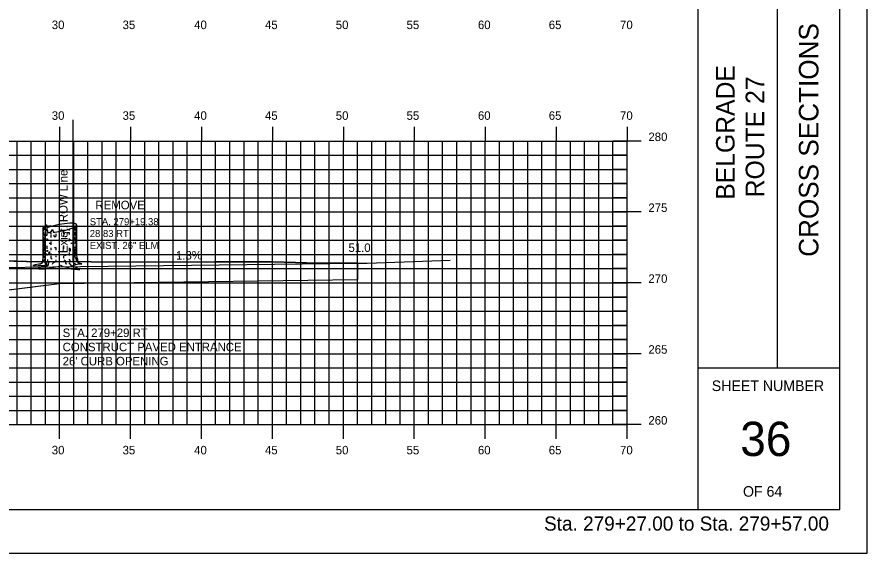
# Model space of a CAD drawing. Extents: x 854899 to 855069, y 366268 to 366378.
# Drawn here: x 855008.8 to 855068.7, y 366268.2 to 366306 of the extents above; entities that cross this region are included whole.
import ezdxf

# ---------------------------------------------------------------- set-up
doc = ezdxf.new("R2010")
doc.units = 0
for name, color, linetype in [('ANNOTATION', 7, 'Continuous'), ('BORDER', 7, 'Continuous'), ('D_Roadway_Drive_Gravel_RT', 7, 'Continuous'), ('D_Roadway_Drive_SubGrade', 7, 'Continuous'), ('D_Text_Monospaced', 7, 'Continuous'), ('D_Text_Standard', 7, 'Continuous'), ('E_ROW_Line', 7, 'Continuous'), ('H_V ANNOTATION', 7, 'Continuous'), ('HIGHWAY_TITLE', 7, 'Continuous'), ('JUNK COM EXC', 7, 'Continuous'), ('MAJOR', 7, 'Continuous'), ('MINOR', 7, 'Continuous'), ('PLOT BOUNDARY', 7, 'Continuous'), ('S_Roadway_Centerline', 7, 'Continuous'), ('S_Trees_Decid_Pay', 7, 'Continuous')]:
    doc.layers.add(name, color=color, linetype=linetype)

msp = doc.modelspace()

# ---------------------------------------------------------------- linework, layer by layer
at = {"layer": 'BORDER'}
for p, q in [((855056.774, 366271.236), (855056.774, 366376.239)), ((855066.774, 366271.236), (855066.774, 366376.236)), ((855062.365, 366281.239), (855062.365, 366316.239)), ((855056.774, 366281.239), (855066.774, 366281.239)), ((854906.774, 366271.236), (855066.774, 366271.236))]:
    msp.add_line(p, q, dxfattribs=at)
at = {"layer": 'D_Roadway_Drive_Gravel_RT'}
for p, q in [((855005.774, 366288.293), (855032.774, 366288.63)), ((855011.774, 366287.201), (855032.774, 366287.463))]:
    msp.add_line(p, q, dxfattribs=at)
at = {"layer": 'D_Roadway_Drive_SubGrade'}
for p, q in [((855032.774, 366288.63), (855032.774, 366287.463)), ((855001.774, 366285.94), (855011.774, 366287.201))]:
    msp.add_line(p, q, dxfattribs=at)
at = {"layer": 'E_ROW_Line'}
msp.add_line((855012.733, 366288.733), (855012.733, 366298.733), dxfattribs=at)
at = {"layer": 'JUNK COM EXC'}
msp.add_lwpolyline([(855001.774, 366285.94), (855011.774, 366287.201), (855032.774, 366287.463), (855032.774, 366288.63), (855029.947, 366288.626), (855028.392, 366288.676), (855026.837, 366288.727), (855022.702, 366288.715), (855018.567, 366288.702), (855014.002, 366288.726), (855009.438, 366288.75), (855008.079, 366288.784), (855006.72, 366288.819), (855003.306, 366288.619), (855001.774, 366288.529)], close=True, dxfattribs=at)
at = {"layer": 'MAJOR'}
for p, q in [((855011.774, 366298.238), (855011.774, 366297.236)), ((855016.774, 366298.238), (855016.774, 366297.236)), ((855021.774, 366298.238), (855021.774, 366297.236)), ((855026.774, 366298.238), (855026.774, 366297.236)), ((855031.774, 366298.238), (855031.774, 366297.236)), ((855036.774, 366298.238), (855036.774, 366297.236)), ((855041.774, 366298.238), (855041.774, 366297.236)), ((855046.774, 366298.238), (855046.774, 366297.236)), ((855051.774, 366298.238), (855051.774, 366297.236)), ((854911.774, 366297.236), (855051.774, 366297.236)), ((854911.774, 366297.236), (855051.774, 366297.236)), ((855011.774, 366277.236), (855011.774, 366297.236)), ((855016.774, 366277.236), (855016.774, 366297.236)), ((855021.774, 366277.236), (855021.774, 366297.236)), ((855026.774, 366277.236), (855026.774, 366297.236)), ((855031.774, 366277.236), (855031.774, 366297.236)), ((855036.774, 366277.236), (855036.774, 366297.236)), ((855041.774, 366277.236), (855041.774, 366297.236)), ((855046.774, 366277.236), (855046.774, 366297.236)), ((855052.776, 366297.236), (855050.772, 366297.236)), ((855051.774, 366277.236), (855051.774, 366297.236)), ((855051.774, 366277.236), (855051.774, 366297.236)), ((854911.774, 366292.236), (855051.774, 366292.236)), ((855052.776, 366292.236), (855050.772, 366292.236)), ((854911.774, 366287.236), (855051.774, 366287.236)), ((855052.776, 366287.236), (855050.772, 366287.236)), ((854911.774, 366282.236), (855051.774, 366282.236)), ((855052.776, 366282.236), (855050.772, 366282.236)), ((854911.774, 366277.236), (855051.774, 366277.236)), ((854911.774, 366277.236), (855051.774, 366277.236)), ((855011.774, 366276.234), (855011.774, 366277.236)), ((855016.774, 366276.234), (855016.774, 366277.236)), ((855021.774, 366276.234), (855021.774, 366277.236)), ((855026.774, 366276.234), (855026.774, 366277.236)), ((855031.774, 366276.234), (855031.774, 366277.236)), ((855036.774, 366276.234), (855036.774, 366277.236)), ((855041.774, 366276.234), (855041.774, 366277.236)), ((855046.774, 366276.234), (855046.774, 366277.236)), ((855052.776, 366277.236), (855050.772, 366277.236)), ((855051.774, 366276.234), (855051.774, 366277.236))]:
    msp.add_line(p, q, dxfattribs=at)
at = {"layer": 'MINOR'}
for p, q in [((855008.774, 366277.236), (855008.774, 366297.236)), ((855009.774, 366277.236), (855009.774, 366297.236)), ((855010.774, 366277.236), (855010.774, 366297.236)), ((855012.774, 366277.236), (855012.774, 366297.236)), ((855013.774, 366277.236), (855013.774, 366297.236)), ((855014.774, 366277.236), (855014.774, 366297.236)), ((855015.774, 366277.236), (855015.774, 366297.236)), ((855017.774, 366277.236), (855017.774, 366297.236)), ((855018.774, 366277.236), (855018.774, 366297.236)), ((855019.774, 366277.236), (855019.774, 366297.236)), ((855020.774, 366277.236), (855020.774, 366297.236)), ((855022.774, 366277.236), (855022.774, 366297.236)), ((855023.774, 366277.236), (855023.774, 366297.236)), ((855024.774, 366277.236), (855024.774, 366297.236)), ((855025.774, 366277.236), (855025.774, 366297.236)), ((855027.774, 366277.236), (855027.774, 366297.236)), ((855028.774, 366277.236), (855028.774, 366297.236)), ((855029.774, 366277.236), (855029.774, 366297.236)), ((855030.774, 366277.236), (855030.774, 366297.236)), ((855032.774, 366277.236), (855032.774, 366297.236)), ((855033.774, 366277.236), (855033.774, 366297.236)), ((855034.774, 366277.236), (855034.774, 366297.236)), ((855035.774, 366277.236), (855035.774, 366297.236)), ((855037.774, 366277.236), (855037.774, 366297.236)), ((855038.774, 366277.236), (855038.774, 366297.236)), ((855039.774, 366277.236), (855039.774, 366297.236)), ((855040.774, 366277.236), (855040.774, 366297.236)), ((855042.774, 366277.236), (855042.774, 366297.236)), ((855043.774, 366277.236), (855043.774, 366297.236)), ((855044.774, 366277.236), (855044.774, 366297.236)), ((855045.774, 366277.236), (855045.774, 366297.236)), ((855047.774, 366277.236), (855047.774, 366297.236)), ((855048.774, 366277.236), (855048.774, 366297.236)), ((855049.774, 366277.236), (855049.774, 366297.236)), ((855050.774, 366277.236), (855050.774, 366297.236)), ((854911.774, 366296.236), (855051.774, 366296.236)), ((855051.774, 366296.236), (855050.772, 366296.236)), ((854911.774, 366295.236), (855051.774, 366295.236)), ((855051.774, 366295.236), (855050.772, 366295.236)), ((854911.774, 366294.236), (855051.774, 366294.236)), ((855051.774, 366294.236), (855050.772, 366294.236)), ((854911.774, 366293.236), (855051.774, 366293.236)), ((855051.774, 366293.236), (855050.772, 366293.236)), ((854911.774, 366291.236), (855051.774, 366291.236)), ((855051.774, 366291.236), (855050.772, 366291.236)), ((854911.774, 366290.236), (855051.774, 366290.236)), ((855051.774, 366290.236), (855050.772, 366290.236)), ((854911.774, 366289.236), (855051.774, 366289.236)), ((855051.774, 366289.236), (855050.772, 366289.236)), ((854911.774, 366288.236), (855051.774, 366288.236)), ((855051.774, 366288.236), (855050.772, 366288.236)), ((854911.774, 366286.236), (855051.774, 366286.236)), ((855051.774, 366286.236), (855050.772, 366286.236)), ((854911.774, 366285.236), (855051.774, 366285.236)), ((855051.774, 366285.236), (855050.772, 366285.236)), ((854911.774, 366284.236), (855051.774, 366284.236)), ((855051.774, 366284.236), (855050.772, 366284.236)), ((854911.774, 366283.236), (855051.774, 366283.236)), ((855051.774, 366283.236), (855050.772, 366283.236)), ((854911.774, 366281.236), (855051.774, 366281.236)), ((855051.774, 366281.236), (855050.772, 366281.236)), ((854911.774, 366280.236), (855051.774, 366280.236)), ((855051.774, 366280.236), (855050.772, 366280.236)), ((854911.774, 366279.236), (855051.774, 366279.236)), ((855051.774, 366279.236), (855050.772, 366279.236)), ((854911.774, 366278.236), (855051.774, 366278.236)), ((855051.774, 366278.236), (855050.772, 366278.236))]:
    msp.add_line(p, q, dxfattribs=at)
at = {"layer": 'PLOT BOUNDARY'}
msp.add_lwpolyline([(854898.681, 366268.177), (855068.681, 366268.177), (855068.681, 366378.177), (854898.681, 366378.177)], close=True, dxfattribs=at)
at = {"layer": 'S_Roadway_Centerline'}
msp.add_lwpolyline([(855006.72, 366288.819), (855009.438, 366288.75), (855018.567, 366288.702), (855026.837, 366288.727), (855029.947, 366288.626), (855033.448, 366288.631), (855039.299, 366288.845)], dxfattribs=at)
at = {"layer": 'S_Trees_Decid_Pay'}
for p, q in [((855010.652, 366290.831), (855010.652, 366290.577)), ((855010.738, 366290.686), (855010.738, 366290.474)), ((855010.802, 366291.031), (855010.802, 366290.857)), ((855010.887, 366290.783), (855010.887, 366290.578)), ((855011.148, 366290.785), (855011.148, 366290.665)), ((855011.513, 366290.686), (855011.513, 366290.506)), ((855012.059, 366290.922), (855012.059, 366290.642)), ((855012.442, 366291.024), (855012.442, 366290.937)), ((855012.442, 366290.796), (855012.442, 366290.657)), ((855012.714, 366290.937), (855012.714, 366290.745)), ((855012.847, 366291.19), (855012.847, 366290.937)), ((855012.847, 366290.84), (855012.847, 366290.577)), ((855012.927, 366291.235), (855012.927, 366291.114)), ((855012.927, 366291.062), (855012.927, 366290.848)), ((855012.927, 366290.803), (855012.927, 366290.465)), ((855010.652, 366290.48), (855010.652, 366290.01)), ((855010.738, 366290.408), (855010.738, 366290.26)), ((855010.738, 366290.083), (855010.738, 366289.782)), ((855010.887, 366290.371), (855010.887, 366290.216)), ((855011.148, 366290.613), (855011.148, 366290.428)), ((855011.148, 366290.142), (855011.148, 366289.914)), ((855011.386, 366290.513), (855011.391, 366290.62)), ((855012.059, 366290.577), (855012.059, 366290.474)), ((855012.442, 366290.371), (855012.442, 366290.179)), ((855012.714, 366290.494), (855012.714, 366290.216)), ((855012.714, 366290.171), (855012.714, 366290.062)), ((855012.847, 366290.48), (855012.847, 366290.171)), ((855012.847, 366290.083), (855012.847, 366290.016)), ((855012.927, 366290.348), (855012.927, 366289.987)), ((855010.652, 366289.959), (855010.652, 366289.825)), ((855010.652, 366289.768), (855010.652, 366289.442)), ((855010.738, 366289.745), (855010.738, 366289.502)), ((855010.887, 366289.854), (855010.887, 366289.634)), ((855010.887, 366289.534), (855010.887, 366289.413)), ((855011.148, 366289.716), (855011.148, 366289.531)), ((855011.513, 366289.728), (855011.513, 366289.531)), ((855012.059, 366289.862), (855012.059, 366289.642)), ((855012.442, 366289.699), (855012.442, 366289.491)), ((855012.714, 366289.928), (855012.714, 366289.699)), ((855012.847, 366289.782), (855012.847, 366289.685)), ((855012.847, 366289.634), (855012.847, 366289.274)), ((855012.927, 366289.951), (855012.927, 366289.502)), ((855010.656, 366288.89), (855010.641, 366288.773)), ((855010.652, 366289.413), (855010.652, 366288.993)), ((855010.738, 366289.391), (855010.738, 366289.251)), ((855010.738, 366289.119), (855010.738, 366288.963)), ((855010.887, 366289.262), (855010.887, 366289.164)), ((855011.148, 366289.296), (855011.148, 366289.219)), ((855011.148, 366289.142), (855011.148, 366288.968)), ((855011.513, 366289.148), (855011.513, 366289.045)), ((855012.059, 366289.142), (855012.059, 366288.968)), ((855012.437, 366288.913), (855012.517, 366288.781)), ((855012.442, 366289.37), (855012.442, 366289.171)), ((855012.714, 366289.37), (855012.714, 366288.987)), ((855012.847, 366289.222), (855012.847, 366289.055)), ((855012.927, 366289.436), (855012.927, 366289.154))]:
    msp.add_line(p, q, dxfattribs=at)
for points in [[(855010.602, 366291.106), (855010.602, 366288.968), (855010.582, 366288.827), (855010.576, 366288.701), (855010.532, 366288.614), (855010.44, 366288.565), (855010.304, 366288.565), (855010.061, 366288.509), (855009.894, 366288.46), (855010.036, 366288.429), (855010.273, 366288.466), (855010.483, 366288.454), (855010.744, 366288.46), (855010.868, 366288.478), (855010.899, 366288.436), (855010.961, 366288.478), (855010.862, 366288.411), (855010.627, 366288.386), (855010.397, 366288.324), (855010.267, 366288.254), (855010.366, 366288.211), (855010.788, 366288.23), (855011.066, 366288.273), (855011.364, 366288.349), (855011.65, 366288.386), (855011.755, 366288.386), (855011.774, 366288.466), (855011.842, 366288.472), (855012.009, 366288.386), (855012.295, 366288.33), (855012.593, 366288.223), (855013.053, 366288.174), (855013.207, 366288.186), (855012.865, 366288.337), (855012.662, 366288.367), (855012.673, 366288.442), (855012.933, 366288.541), (855013.109, 366288.571), (855013.349, 366288.583), (855013.151, 366288.621), (855013.089, 366288.657), (855013.065, 366288.744), (855013.053, 366288.913), (855013.007, 366288.999), (855012.979, 366289.24), (855012.979, 366291.326)], [(855010.958, 366290.778), (855010.95, 366290.922), (855010.905, 366290.915), (855010.891, 366291.289), (855010.796, 366291.297), (855010.782, 366291.377), (855010.744, 366291.04), (855010.699, 366291.134), (855010.679, 366290.98), (855010.602, 366291.106), (855010.608, 366290.916)], [(855010.981, 366291.144), (855011.002, 366291.252), (855011.133, 366291.283), (855011.141, 366291.195)], [(855010.602, 366291.106), (855010.648, 366291.129), (855010.67, 366291.194), (855010.722, 366291.217), (855010.755, 366291.142)], [(855011.12, 366290.783), (855011.156, 366290.886), (855011.222, 366290.892), (855011.222, 366290.974), (855011.296, 366290.98), (855011.321, 366290.8)], [(855011.01, 366289.413), (855011.002, 366289.339), (855011.076, 366289.333), (855011.09, 366289.45)], [(855012.555, 366289.505), (855012.554, 366289.582), (855012.546, 366289.648)], [(855010.722, 366288.898), (855010.715, 366288.773), (855010.633, 366288.678)], [(855010.868, 366288.478), (855010.887, 366288.657), (855010.948, 366288.794), (855010.942, 366288.894)], [(855011.511, 366288.861), (855011.494, 366288.707), (855011.296, 366288.627), (855011.251, 366288.524)], [(855012.076, 366288.853), (855012.179, 366288.802), (855012.194, 366288.596), (855012.297, 366288.567)], [(855012.731, 366288.927), (855012.731, 366288.722), (855012.789, 366288.612), (855012.886, 366288.596)], [(855012.872, 366289.001), (855012.943, 366288.898), (855012.943, 366288.773)], [(855012.929, 366289.082), (855012.989, 366288.921), (855013.003, 366288.796), (855012.995, 366288.699)], [(855011.059, 366288.726), (855010.985, 366288.657), (855010.967, 366288.559), (855010.961, 366288.478)], [(855012.662, 366288.367), (855012.575, 366288.509), (855012.443, 366288.652)]]:
    msp.add_lwpolyline(points, dxfattribs=at)
for centre, radius, start, end in [((855012.892, 366285.325), 6.126, 100.77788, 107.86134), ((855012.892, 366285.325), 6.126, 93.69441, 100.77788), ((855012.581, 366290.141), 1.299, 78.27788, 93.69441), ((855012.747, 366290.944), 0.48, 69.98432, 78.27788), ((855012.62, 366291.614), 0.48, 303.27788, 311.57144), ((855012.855, 366291.24), 0.164, 55.77788, 69.98432), ((855012.829, 366291.378), 0.164, 311.57144, 325.77788), ((855012.887, 366291.287), 0.107, 45.9547, 55.77788), ((855012.917, 366291.318), 0.0645, 33.27788, 45.9547), ((855012.876, 366291.346), 0.107, 325.77788, 335.60106), ((855012.926, 366291.323), 0.0544, 22.46002, 33.27788), ((855012.915, 366291.328), 0.0645, 335.60106, 348.27788), ((855012.933, 366291.326), 0.0467, 10.77788, 22.46002), ((855012.925, 366291.326), 0.0544, 348.27788, 359.09574), ((855012.933, 366291.326), 0.0467, 359.09574, 10.77788), ((855010.65, 366290.737), 0.0476, 180, 191.68146), ((855010.658, 366290.739), 0.0554, 191.68146, 202.5), ((855010.667, 366290.743), 0.0657, 202.5, 215.17372), ((855010.702, 366290.768), 0.109, 215.17372, 225), ((855010.743, 366290.808), 0.166, 225, 239.19244), ((855011.412, 366289.918), 1.299, 107.86134, 113.3069), ((855011.001, 366292.077), 1.299, 268.12894, 273.69441), ((855010.69, 366296.893), 6.126, 273.69441, 274.02462), ((855010.69, 366296.893), 6.126, 275.91473, 280.77788), ((855010.69, 366296.893), 6.126, 280.77788, 287.86134), ((855011.792, 366296.676), 5.916, 274.95145, 276.30875), ((855012.17, 366292.299), 1.299, 287.86134, 303.27788), ((855012.368, 366292.088), 1.292, 285.56513, 289.09156), ((855012.676, 366291.081), 0.484, 297.41617, 300.80756), ((855012.839, 366290.808), 0.166, 300.80756, 315), ((855012.84, 366291.069), 0.166, 301.67004, 315), ((855012.879, 366290.768), 0.109, 315, 324.82628), ((855012.88, 366291.029), 0.109, 315, 324.82628), ((855012.915, 366290.743), 0.0657, 324.82628, 337.5), ((855012.916, 366291.004), 0.0657, 324.82628, 337.5), ((855012.924, 366290.739), 0.0554, 337.5, 348.31854), ((855012.925, 366291), 0.0554, 337.5, 348.31854), ((855010.65, 366290.216), 0.0476, 180, 191.68146), ((855010.658, 366290.218), 0.0554, 191.68146, 202.5), ((855010.667, 366290.222), 0.0657, 202.5, 215.17372), ((855010.702, 366290.247), 0.109, 215.17372, 225), ((855010.743, 366290.287), 0.166, 225, 239.19244), ((855010.743, 366290.545), 0.166, 237.03779, 239.19244), ((855010.906, 366290.818), 0.484, 239.19244, 247.5), ((855010.906, 366290.56), 0.484, 239.19244, 245.77245), ((855011.215, 366291.564), 1.292, 247.5, 248.35373), ((855011.215, 366291.307), 1.292, 247.5, 248.48417), ((855011.215, 366291.828), 1.292, 250.61187, 255.28558), ((855011.215, 366291.564), 1.292, 255.28558, 259.26323), ((855011.791, 366296.415), 5.916, 266.07764, 267.30434), ((855011.791, 366296.152), 5.916, 270.1162, 271.77083), ((855011.791, 366296.415), 5.916, 273.53821, 274.89239), ((855011.791, 366296.152), 5.916, 276.31835, 277.15463), ((855012.367, 366291.564), 1.292, 277.15463, 278.36619), ((855012.367, 366291.307), 1.292, 279.25654, 285.6105), ((855012.367, 366291.828), 1.292, 288.08294, 292.5), ((855012.367, 366291.564), 1.292, 291.8071, 292.5), ((855012.676, 366290.818), 0.484, 292.5, 300.80756), ((855012.676, 366290.56), 0.484, 294.63721, 300.80756), ((855012.839, 366290.545), 0.166, 300.80756, 301.6001), ((855012.839, 366290.287), 0.166, 300.80756, 315), ((855012.879, 366290.247), 0.109, 315, 324.82628), ((855012.915, 366290.222), 0.0657, 324.82628, 337.5), ((855012.924, 366290.218), 0.0554, 337.5, 348.31854), ((855010.65, 366289.959), 0.0476, 180, 191.68146), ((855010.65, 366289.693), 0.0476, 180, 191.68146), ((855010.658, 366289.961), 0.0554, 191.68146, 202.5), ((855010.658, 366289.695), 0.0554, 191.68146, 202.5), ((855010.667, 366289.964), 0.0657, 202.5, 215.17372), ((855010.667, 366289.699), 0.0657, 202.5, 215.17372), ((855010.702, 366289.989), 0.109, 215.17372, 225), ((855010.702, 366289.724), 0.109, 215.17372, 225), ((855010.743, 366290.03), 0.166, 225, 239.19244), ((855010.743, 366289.764), 0.166, 225, 239.19244), ((855010.906, 366290.037), 0.484, 239.19244, 247.5), ((855011.215, 366291.049), 1.292, 247.5, 251.79898), ((855011.215, 366290.784), 1.292, 247.5, 248.35373), ((855011.215, 366290.784), 1.292, 255.28558, 259.24628), ((855011.215, 366291.307), 1.292, 261.87258, 262.84538), ((855011.791, 366295.895), 5.916, 262.84537, 263.7595), ((855011.791, 366295.637), 5.916, 266.27211, 267.30434), ((855011.791, 366295.372), 5.916, 268.92065, 270), ((855011.791, 366295.372), 5.916, 270, 270.27568), ((855011.791, 366295.372), 5.916, 276.31835, 277.15463), ((855012.367, 366290.784), 1.292, 277.15463, 278.37952), ((855012.367, 366291.049), 1.292, 285.61049, 290.10015), ((855012.676, 366290.037), 0.484, 292.5, 300.80756), ((855012.839, 366289.764), 0.166, 300.80756, 302.06939), ((855012.839, 366290.03), 0.166, 302.06939, 315), ((855012.879, 366289.989), 0.109, 315, 324.82628), ((855012.915, 366289.964), 0.0657, 324.82628, 337.5), ((855012.924, 366289.961), 0.0554, 337.5, 348.31854), ((855012.924, 366289.695), 0.0554, 337.5, 348.31854), ((855010.65, 366289.164), 0.0476, 180, 191.68146), ((855010.658, 366289.166), 0.0554, 191.68146, 202.5), ((855010.667, 366289.17), 0.0657, 202.5, 215.17372), ((855010.702, 366289.195), 0.109, 215.17372, 225), ((855010.743, 366289.235), 0.166, 225, 239.19244), ((855010.906, 366289.508), 0.484, 239.19244, 247.5), ((855010.906, 366289.766), 0.484, 242.73401, 247.5), ((855011.215, 366290.254), 1.292, 247.5, 248.35373), ((855011.215, 366290.512), 1.292, 251.36642, 255.28558), ((855011.791, 366294.842), 5.916, 263.78314, 264.76555), ((855011.791, 366295.1), 5.916, 273.26366, 274.46102), ((855011.791, 366295.1), 5.916, 276.31835, 277.15463), ((855012.367, 366290.512), 1.292, 277.15463, 278.36619), ((855012.367, 366290.512), 1.292, 285.61049, 289.15336), ((855012.376, 366290.258), 1.292, 291.36963, 292.0604), ((855012.676, 366289.508), 0.484, 292.5, 296.54992), ((855012.839, 366289.493), 0.166, 302.06939, 315), ((855012.879, 366289.452), 0.109, 315, 324.82628), ((855012.915, 366289.427), 0.0657, 324.82628, 337.5), ((855012.924, 366289.423), 0.0554, 337.5, 348.31854)]:
    msp.add_arc(centre, radius, start, end, dxfattribs=at)

# ---------------------------------------------------------------- texts
at = {"layer": 'ANNOTATION'}
for s, p in [('REMOVE', (855014.304, 366292.423)), ('STA. 279+29 RT', (855011.99, 366283.412)), ('CONSTRUCT PAVED ENTRANCE', (855011.99, 366282.412)), ("26' CURB OPENING", (855011.99, 366281.412))]:
    msp.add_text(s, height=0.6, dxfattribs=at).set_placement(p)
at = {"layer": 'BORDER'}
for s, height, rotation, p in [('CROSS SECTIONS', 1.37787, 90, (855065.259, 366289.073)), ('SHEET NUMBER', 0.74527, 360, (855057.74, 366279.603)), ('36', 2.4194, 360, (855059.75, 366275.019)), ('OF 64', 0.7453, 360, (855059.941, 366272.149))]:
    msp.add_text(s, height=height, rotation=rotation, dxfattribs=at).set_placement(p)
at = {"layer": 'D_Text_Monospaced'}
for s, height, p in [('STA. 279+19.38', 0.49998, (855013.901, 366291.3)), ('28.83 RT.', 0.5, (855013.901, 366290.466)), ('EXIST. 26" ELM', 0.49998, (855013.901, 366289.626))]:
    msp.add_text(s, height=height, dxfattribs=at).set_placement(p)
at = {"layer": 'D_Text_Standard'}
msp.add_text('1.3%', height=0.6, rotation=0.7143, dxfattribs=at).set_placement((855019.98, 366288.871))
msp.add_text("51.0'", height=0.6, dxfattribs=at).set_placement((855032.134, 366289.416))
at = {"layer": 'E_ROW_Line'}
msp.add_text('Exist. ROW Line', height=0.6, rotation=90, dxfattribs=at).set_placement((855012.333, 366289.333))
at = {"layer": 'H_V ANNOTATION'}
for s, height, p in [('30', 0.6, (855011.223, 366305.136)), ('35', 0.6, (855016.215, 366305.136)), ('40', 0.6, (855021.26, 366305.136)), ('45', 0.6, (855026.252, 366305.136)), ('50', 0.6, (855031.239, 366305.136)), ('55', 0.6, (855036.231, 366305.136)), ('60', 0.6, (855041.26, 366305.136)), ('65', 0.6, (855046.252, 366305.136)), ('70', 0.6, (855051.276, 366305.136)), ('30', 0.6, (855011.223, 366298.736)), ('35', 0.6, (855016.215, 366298.736)), ('40', 0.6, (855021.26, 366298.736)), ('45', 0.6, (855026.252, 366298.736)), ('50', 0.6, (855031.239, 366298.736)), ('55', 0.6, (855036.231, 366298.736)), ('60', 0.6, (855041.26, 366298.736)), ('65', 0.6, (855046.252, 366298.736)), ('70', 0.6, (855051.276, 366298.736)), ('280', 0.6, (855053.274, 366297.236)), ('275', 0.6, (855053.274, 366292.236)), ('270', 0.6, (855053.274, 366287.236)), ('265', 0.6, (855053.274, 366282.236)), ('260', 0.6, (855053.274, 366277.236)), ('30', 0.6, (855011.223, 366275.136)), ('35', 0.6, (855016.215, 366275.136)), ('40', 0.6, (855021.26, 366275.136)), ('45', 0.6, (855026.252, 366275.136)), ('50', 0.6, (855031.239, 366275.136)), ('55', 0.6, (855036.231, 366275.136)), ('60', 0.6, (855041.26, 366275.136)), ('65', 0.6, (855046.252, 366275.136)), ('70', 0.6, (855051.276, 366275.136)), ('Sta. 279+27.00 to Sta. 279+57.00', 1.0002, (855045.92, 366269.756))]:
    msp.add_text(s, height=height, dxfattribs=at).set_placement(p)
at = {"layer": 'HIGHWAY_TITLE'}
for s, p in [('BELGRADE', (855059.347, 366293.095)), ('ROUTE 27', (855061.434, 366293.269))]:
    msp.add_text(s, height=1.3043, rotation=90, dxfattribs=at).set_placement(p)

doc.saveas('drawing.dxf')
